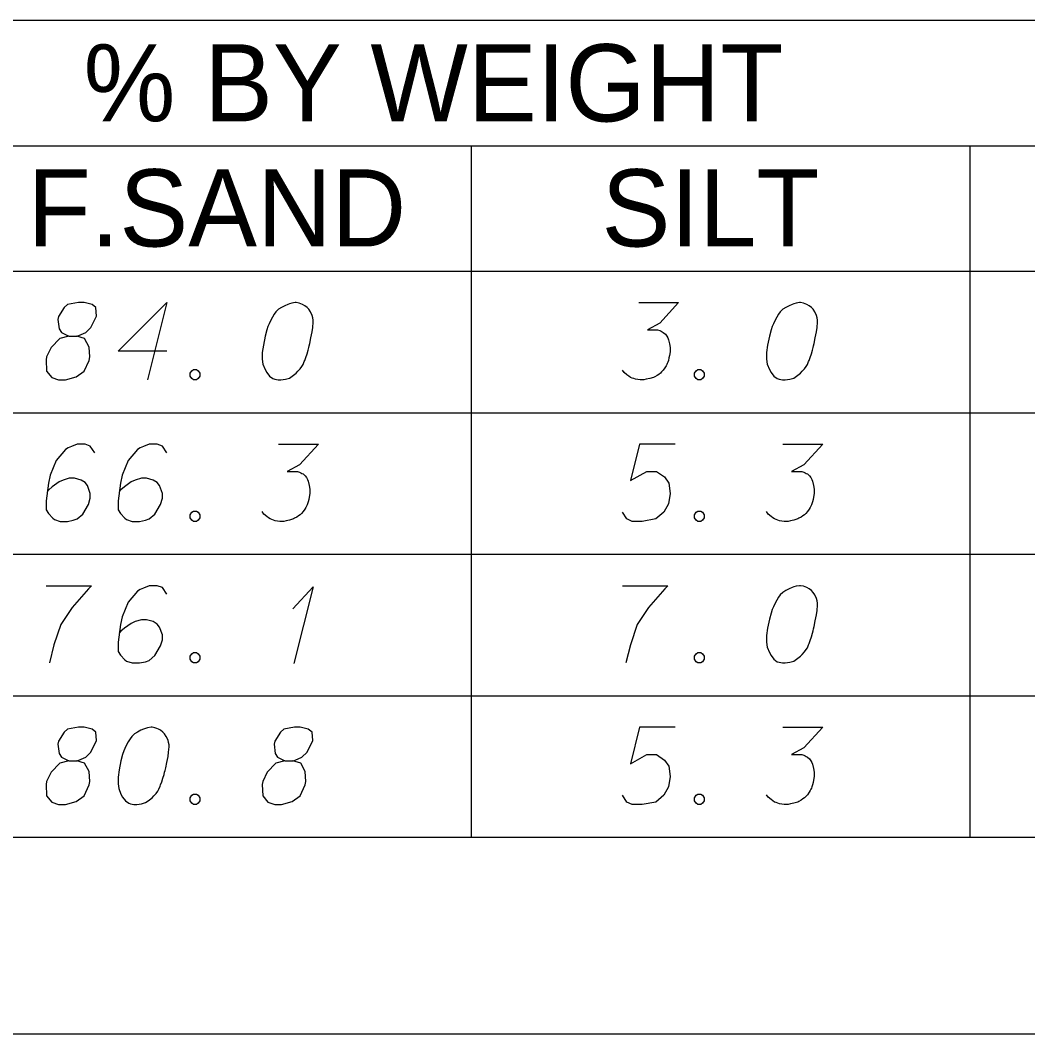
# Model space of a CAD drawing. Extents: x 2074207 to 2076812, y 516372 to 523312.
# Drawn here: x 2076560.1 to 2076622.7, y 516665.2 to 516728.2 of the extents above; entities that cross this region are included whole.
import ezdxf

# ---------------------------------------------------------------- set-up
doc = ezdxf.new("R2010")
doc.units = 0
for name, color, linetype in [('Prop DirtTable_ Soil Test Results - Outline (Major)', 7, 'Continuous'), ('Prop DirtTable_ Soil Test Results - Outline (Minor)', 7, 'Continuous'), ('Prop DirtTable_ Soil Test Results - Tx (Header - Small)', 7, 'Continuous'), ('Prop DirtTable_ Soil Test Results - Tx (Sample Data)', 7, 'Continuous')]:
    doc.layers.add(name, color=color, linetype=linetype)

msp = doc.modelspace()

# ---------------------------------------------------------------- linework, layer by layer
at = {"layer": 'Prop DirtTable_ Soil Test Results - Outline (Major)'}
for p, q in [((2076260.609, 516712.618), (2076811.903, 516712.618)), ((2076260.609, 516712.618), (2076811.903, 516712.618)), ((2076260.609, 516677.418), (2076811.903, 516677.418)), ((2076260.609, 516665.206), (2076811.903, 516665.206))]:
    msp.add_line(p, q, dxfattribs=at)
at = {"layer": 'Prop DirtTable_ Soil Test Results - Outline (Minor)'}
for p, q in [((2076260.609, 516728.218), (2076811.903, 516728.218)), ((2076526.074, 516720.418), (2076731.93, 516720.418)), ((2076588.114, 516720.418), (2076588.114, 516703.818)), ((2076619.134, 516703.818), (2076619.134, 516720.418)), ((2076260.609, 516703.818), (2076811.903, 516703.818)), ((2076260.609, 516703.818), (2076811.903, 516703.818)), ((2076588.114, 516703.818), (2076588.114, 516695.018)), ((2076619.134, 516695.018), (2076619.134, 516703.818)), ((2076260.609, 516695.018), (2076811.903, 516695.018)), ((2076260.609, 516695.018), (2076811.903, 516695.018)), ((2076588.114, 516695.018), (2076588.114, 516686.218)), ((2076619.134, 516686.218), (2076619.134, 516695.018)), ((2076260.609, 516686.218), (2076811.903, 516686.218)), ((2076260.609, 516686.218), (2076811.903, 516686.218)), ((2076588.114, 516686.218), (2076588.114, 516677.418)), ((2076619.134, 516677.418), (2076619.134, 516686.218)), ((2076260.609, 516677.418), (2076811.903, 516677.418))]:
    msp.add_line(p, q, dxfattribs=at)
at = {"layer": 'Prop DirtTable_ Soil Test Results - Tx (Sample Data)'}
for points in [[(2076563.087, 516708.583), (2076563.58, 516708.583), (2076563.722, 516708.621), (2076564.145, 516708.81), (2076564.462, 516709.112), (2076564.815, 516709.83), (2076564.78, 516710.359), (2076564.533, 516710.548), (2076564.039, 516710.662), (2076563.686, 516710.662), (2076563.016, 516710.548), (2076562.804, 516710.359), (2076562.452, 516709.792), (2076562.416, 516709.603), (2076562.487, 516709.036), (2076562.628, 516708.81), (2076563.087, 516708.583), (2076562.522, 516708.432), (2076561.993, 516707.865), (2076561.711, 516707.298), (2076561.676, 516707.109), (2076561.711, 516706.391), (2076562.028, 516706.013), (2076562.452, 516705.862), (2076562.875, 516705.862), (2076563.545, 516706.051), (2076564.039, 516706.391), (2076564.357, 516707.071), (2076564.392, 516707.298), (2076564.357, 516707.903), (2076564.074, 516708.432), (2076563.58, 516708.583)], [(2076569.189, 516707.638), (2076566.156, 516707.638), (2076569.189, 516710.662), (2076567.99, 516705.862)], [(2076577.232, 516710.662), (2076577.162, 516710.662), (2076576.95, 516710.624), (2076576.809, 516710.586), (2076576.703, 516710.548), (2076576.527, 516710.473), (2076576.315, 516710.359), (2076576.139, 516710.246), (2076575.962, 516710.095), (2076575.856, 516709.944), (2076575.751, 516709.755), (2076575.645, 516709.566), (2076575.539, 516709.339), (2076575.468, 516709.188), (2076575.398, 516708.961), (2076575.292, 516708.583), (2076575.186, 516708.016), (2076575.116, 516707.562), (2076575.116, 516707.147), (2076575.151, 516706.844), (2076575.292, 516706.504), (2076575.398, 516706.315), (2076575.574, 516706.088), (2076575.786, 516705.937), (2076575.892, 516705.899), (2076576.103, 516705.862), (2076576.28, 516705.862), (2076576.562, 516705.899), (2076576.809, 516705.975), (2076576.985, 516706.088), (2076577.232, 516706.277), (2076577.338, 516706.391), (2076577.479, 516706.542), (2076577.585, 516706.693), (2076577.655, 516706.807), (2076577.726, 516706.996), (2076577.761, 516707.071), (2076577.832, 516707.26), (2076577.902, 516707.487), (2076577.973, 516707.714), (2076578.008, 516707.865), (2076578.043, 516707.978), (2076578.079, 516708.129), (2076578.149, 516708.47), (2076578.185, 516708.659), (2076578.22, 516708.848), (2076578.255, 516709.112), (2076578.29, 516709.452), (2076578.29, 516709.566), (2076578.255, 516709.717), (2076578.22, 516709.868), (2076578.114, 516710.095), (2076578.008, 516710.246), (2076577.902, 516710.359), (2076577.761, 516710.473), (2076577.62, 516710.548), (2076577.514, 516710.586), (2076577.409, 516710.624), (2076577.232, 516710.662)], [(2076598.539, 516710.662), (2076601.008, 516710.662), (2076599.844, 516709.377), (2076599.068, 516708.961), (2076599.703, 516708.961), (2076599.844, 516708.923), (2076599.914, 516708.885), (2076599.985, 516708.848), (2076600.055, 516708.81), (2076600.197, 516708.696), (2076600.267, 516708.583), (2076600.338, 516708.47), (2076600.373, 516708.356), (2076600.443, 516708.092), (2076600.479, 516707.865), (2076600.479, 516707.751), (2076600.479, 516707.6), (2076600.443, 516707.373), (2076600.408, 516707.222), (2076600.373, 516707.071), (2076600.338, 516706.958), (2076600.302, 516706.882), (2076600.267, 516706.807), (2076600.232, 516706.731), (2076600.161, 516706.618), (2076600.055, 516706.466), (2076599.95, 516706.353), (2076599.879, 516706.277), (2076599.773, 516706.202), (2076599.667, 516706.126), (2076599.526, 516706.051), (2076599.456, 516706.013), (2076599.209, 516705.937), (2076598.997, 516705.899), (2076598.856, 516705.862), (2076598.609, 516705.862), (2076598.327, 516705.899), (2076598.221, 516705.937), (2076598.115, 516705.975), (2076598.009, 516706.013), (2076597.904, 516706.088), (2076597.798, 516706.164), (2076597.621, 516706.315), (2076597.516, 516706.466)], [(2076608.592, 516710.662), (2076608.522, 516710.662), (2076608.31, 516710.624), (2076608.169, 516710.586), (2076608.063, 516710.548), (2076607.887, 516710.473), (2076607.675, 516710.359), (2076607.499, 516710.246), (2076607.322, 516710.095), (2076607.216, 516709.944), (2076607.111, 516709.755), (2076607.005, 516709.566), (2076606.899, 516709.339), (2076606.828, 516709.188), (2076606.758, 516708.961), (2076606.652, 516708.583), (2076606.546, 516708.016), (2076606.476, 516707.562), (2076606.476, 516707.147), (2076606.511, 516706.844), (2076606.652, 516706.504), (2076606.758, 516706.315), (2076606.934, 516706.088), (2076607.146, 516705.937), (2076607.252, 516705.899), (2076607.463, 516705.862), (2076607.64, 516705.862), (2076607.922, 516705.899), (2076608.169, 516705.975), (2076608.345, 516706.088), (2076608.592, 516706.277), (2076608.698, 516706.391), (2076608.839, 516706.542), (2076608.945, 516706.693), (2076609.015, 516706.807), (2076609.086, 516706.996), (2076609.121, 516707.071), (2076609.192, 516707.26), (2076609.262, 516707.487), (2076609.333, 516707.714), (2076609.368, 516707.865), (2076609.403, 516707.978), (2076609.439, 516708.129), (2076609.509, 516708.47), (2076609.545, 516708.659), (2076609.58, 516708.848), (2076609.615, 516709.112), (2076609.65, 516709.452), (2076609.65, 516709.566), (2076609.615, 516709.717), (2076609.58, 516709.868), (2076609.474, 516710.095), (2076609.368, 516710.246), (2076609.262, 516710.359), (2076609.121, 516710.473), (2076608.98, 516710.548), (2076608.874, 516710.586), (2076608.769, 516710.624), (2076608.592, 516710.662)], [(2076570.847, 516706.504), (2076571.024, 516706.504), (2076571.129, 516706.429), (2076571.235, 516706.277), (2076571.235, 516706.088), (2076571.129, 516705.937), (2076571.024, 516705.862), (2076570.847, 516705.862), (2076570.741, 516705.937), (2076570.636, 516706.088), (2076570.636, 516706.277), (2076570.741, 516706.429), (2076570.847, 516706.504)], [(2076602.207, 516706.504), (2076602.384, 516706.504), (2076602.489, 516706.429), (2076602.595, 516706.277), (2076602.595, 516706.088), (2076602.489, 516705.937), (2076602.384, 516705.862), (2076602.207, 516705.862), (2076602.101, 516705.937), (2076601.996, 516706.088), (2076601.996, 516706.277), (2076602.101, 516706.429), (2076602.207, 516706.504)], [(2076564.709, 516701.333), (2076564.427, 516701.748), (2076564.11, 516701.862), (2076563.616, 516701.862), (2076563.263, 516701.711), (2076563.051, 516701.635), (2076562.875, 516701.522), (2076562.311, 516700.841), (2076561.923, 516699.934), (2076561.817, 516699.443), (2076561.676, 516698.347), (2076561.676, 516697.78), (2076561.817, 516697.553), (2076562.099, 516697.251), (2076562.205, 516697.175), (2076562.558, 516697.062), (2076563.016, 516697.062), (2076563.369, 516697.137), (2076563.616, 516697.213), (2076563.969, 516697.515), (2076564.321, 516698.12), (2076564.427, 516698.498), (2076564.427, 516698.8), (2076564.251, 516699.292), (2076564.11, 516699.481), (2076563.863, 516699.632), (2076563.439, 516699.745), (2076563.122, 516699.745), (2076562.734, 516699.632), (2076562.487, 516699.518), (2076562.064, 516699.216), (2076561.852, 516699.027), (2076561.746, 516698.914)], [(2076569.189, 516701.333), (2076568.907, 516701.748), (2076568.59, 516701.862), (2076568.096, 516701.862), (2076567.743, 516701.711), (2076567.531, 516701.635), (2076567.355, 516701.522), (2076566.791, 516700.841), (2076566.403, 516699.934), (2076566.297, 516699.443), (2076566.156, 516698.347), (2076566.156, 516697.78), (2076566.297, 516697.553), (2076566.579, 516697.251), (2076566.685, 516697.175), (2076567.038, 516697.062), (2076567.496, 516697.062), (2076567.849, 516697.137), (2076568.096, 516697.213), (2076568.449, 516697.515), (2076568.801, 516698.12), (2076568.907, 516698.498), (2076568.907, 516698.8), (2076568.731, 516699.292), (2076568.59, 516699.481), (2076568.343, 516699.632), (2076567.919, 516699.745), (2076567.602, 516699.745), (2076567.214, 516699.632), (2076566.967, 516699.518), (2076566.544, 516699.216), (2076566.332, 516699.027), (2076566.226, 516698.914)], [(2076576.139, 516701.862), (2076578.608, 516701.862), (2076577.444, 516700.577), (2076576.668, 516700.161), (2076577.303, 516700.161), (2076577.444, 516700.123), (2076577.514, 516700.085), (2076577.585, 516700.048), (2076577.655, 516700.01), (2076577.797, 516699.896), (2076577.867, 516699.783), (2076577.938, 516699.67), (2076577.973, 516699.556), (2076578.043, 516699.292), (2076578.079, 516699.065), (2076578.079, 516698.951), (2076578.079, 516698.8), (2076578.043, 516698.573), (2076578.008, 516698.422), (2076577.973, 516698.271), (2076577.938, 516698.158), (2076577.902, 516698.082), (2076577.867, 516698.007), (2076577.832, 516697.931), (2076577.761, 516697.818), (2076577.655, 516697.666), (2076577.55, 516697.553), (2076577.479, 516697.477), (2076577.373, 516697.402), (2076577.267, 516697.326), (2076577.126, 516697.251), (2076577.056, 516697.213), (2076576.809, 516697.137), (2076576.597, 516697.099), (2076576.456, 516697.062), (2076576.209, 516697.062), (2076575.927, 516697.099), (2076575.821, 516697.137), (2076575.715, 516697.175), (2076575.609, 516697.213), (2076575.504, 516697.288), (2076575.398, 516697.364), (2076575.221, 516697.515), (2076575.116, 516697.666)], [(2076600.796, 516701.862), (2076598.574, 516701.862), (2076598.009, 516699.594), (2076599.032, 516700.161), (2076599.632, 516700.161), (2076600.126, 516699.821), (2076600.408, 516699.443), (2076600.479, 516698.8), (2076600.373, 516698.158), (2076600.091, 516697.629), (2076599.597, 516697.213), (2076598.75, 516697.062), (2076598.115, 516697.062), (2076597.798, 516697.213), (2076597.516, 516697.629)], [(2076607.499, 516701.862), (2076609.968, 516701.862), (2076608.804, 516700.577), (2076608.028, 516700.161), (2076608.663, 516700.161), (2076608.804, 516700.123), (2076608.874, 516700.085), (2076608.945, 516700.048), (2076609.015, 516700.01), (2076609.157, 516699.896), (2076609.227, 516699.783), (2076609.298, 516699.67), (2076609.333, 516699.556), (2076609.403, 516699.292), (2076609.439, 516699.065), (2076609.439, 516698.951), (2076609.439, 516698.8), (2076609.403, 516698.573), (2076609.368, 516698.422), (2076609.333, 516698.271), (2076609.298, 516698.158), (2076609.262, 516698.082), (2076609.227, 516698.007), (2076609.192, 516697.931), (2076609.121, 516697.818), (2076609.015, 516697.666), (2076608.91, 516697.553), (2076608.839, 516697.477), (2076608.733, 516697.402), (2076608.627, 516697.326), (2076608.486, 516697.251), (2076608.416, 516697.213), (2076608.169, 516697.137), (2076607.957, 516697.099), (2076607.816, 516697.062), (2076607.569, 516697.062), (2076607.287, 516697.099), (2076607.181, 516697.137), (2076607.075, 516697.175), (2076606.969, 516697.213), (2076606.864, 516697.288), (2076606.758, 516697.364), (2076606.581, 516697.515), (2076606.476, 516697.666)], [(2076570.847, 516697.704), (2076571.024, 516697.704), (2076571.129, 516697.629), (2076571.235, 516697.477), (2076571.235, 516697.288), (2076571.129, 516697.137), (2076571.024, 516697.062), (2076570.847, 516697.062), (2076570.741, 516697.137), (2076570.636, 516697.288), (2076570.636, 516697.477), (2076570.741, 516697.629), (2076570.847, 516697.704)], [(2076602.207, 516697.704), (2076602.384, 516697.704), (2076602.489, 516697.629), (2076602.595, 516697.477), (2076602.595, 516697.288), (2076602.489, 516697.137), (2076602.384, 516697.062), (2076602.207, 516697.062), (2076602.101, 516697.137), (2076601.996, 516697.288), (2076601.996, 516697.477), (2076602.101, 516697.629), (2076602.207, 516697.704)], [(2076561.676, 516693.062), (2076564.498, 516693.062), (2076564.321, 516692.873), (2076563.298, 516691.701), (2076562.593, 516690.643), (2076562.169, 516689.396), (2076561.887, 516688.262)], [(2076569.189, 516692.533), (2076568.907, 516692.948), (2076568.59, 516693.062), (2076568.096, 516693.062), (2076567.743, 516692.911), (2076567.531, 516692.835), (2076567.355, 516692.722), (2076566.791, 516692.041), (2076566.403, 516691.134), (2076566.297, 516690.643), (2076566.156, 516689.547), (2076566.156, 516688.98), (2076566.297, 516688.753), (2076566.579, 516688.451), (2076566.685, 516688.375), (2076567.038, 516688.262), (2076567.496, 516688.262), (2076567.849, 516688.337), (2076568.096, 516688.413), (2076568.449, 516688.715), (2076568.801, 516689.32), (2076568.907, 516689.698), (2076568.907, 516690), (2076568.731, 516690.492), (2076568.59, 516690.681), (2076568.343, 516690.832), (2076567.919, 516690.945), (2076567.602, 516690.945), (2076567.214, 516690.832), (2076566.967, 516690.718), (2076566.544, 516690.416), (2076566.332, 516690.227), (2076566.226, 516690.114)], [(2076577.02, 516691.625), (2076578.29, 516692.986), (2076577.091, 516688.224)], [(2076597.516, 516693.062), (2076600.338, 516693.062), (2076600.161, 516692.873), (2076599.138, 516691.701), (2076598.433, 516690.643), (2076598.009, 516689.396), (2076597.727, 516688.262)], [(2076608.592, 516693.062), (2076608.522, 516693.062), (2076608.31, 516693.024), (2076608.169, 516692.986), (2076608.063, 516692.948), (2076607.887, 516692.873), (2076607.675, 516692.759), (2076607.499, 516692.646), (2076607.322, 516692.495), (2076607.216, 516692.344), (2076607.111, 516692.155), (2076607.005, 516691.966), (2076606.899, 516691.739), (2076606.828, 516691.588), (2076606.758, 516691.361), (2076606.652, 516690.983), (2076606.546, 516690.416), (2076606.476, 516689.962), (2076606.476, 516689.547), (2076606.511, 516689.244), (2076606.652, 516688.904), (2076606.758, 516688.715), (2076606.934, 516688.488), (2076607.146, 516688.337), (2076607.252, 516688.299), (2076607.463, 516688.262), (2076607.64, 516688.262), (2076607.922, 516688.299), (2076608.169, 516688.375), (2076608.345, 516688.488), (2076608.592, 516688.677), (2076608.698, 516688.791), (2076608.839, 516688.942), (2076608.945, 516689.093), (2076609.015, 516689.207), (2076609.086, 516689.396), (2076609.121, 516689.471), (2076609.192, 516689.66), (2076609.262, 516689.887), (2076609.333, 516690.114), (2076609.368, 516690.265), (2076609.403, 516690.378), (2076609.439, 516690.529), (2076609.509, 516690.87), (2076609.545, 516691.059), (2076609.58, 516691.248), (2076609.615, 516691.512), (2076609.65, 516691.852), (2076609.65, 516691.966), (2076609.615, 516692.117), (2076609.58, 516692.268), (2076609.474, 516692.495), (2076609.368, 516692.646), (2076609.262, 516692.759), (2076609.121, 516692.873), (2076608.98, 516692.948), (2076608.874, 516692.986), (2076608.769, 516693.024), (2076608.592, 516693.062)], [(2076570.847, 516688.904), (2076571.024, 516688.904), (2076571.129, 516688.829), (2076571.235, 516688.677), (2076571.235, 516688.488), (2076571.129, 516688.337), (2076571.024, 516688.262), (2076570.847, 516688.262), (2076570.741, 516688.337), (2076570.636, 516688.488), (2076570.636, 516688.677), (2076570.741, 516688.829), (2076570.847, 516688.904)], [(2076602.207, 516688.904), (2076602.384, 516688.904), (2076602.489, 516688.829), (2076602.595, 516688.677), (2076602.595, 516688.488), (2076602.489, 516688.337), (2076602.384, 516688.262), (2076602.207, 516688.262), (2076602.101, 516688.337), (2076601.996, 516688.488), (2076601.996, 516688.677), (2076602.101, 516688.829), (2076602.207, 516688.904)], [(2076563.087, 516682.183), (2076563.58, 516682.183), (2076563.722, 516682.221), (2076564.145, 516682.41), (2076564.462, 516682.712), (2076564.815, 516683.43), (2076564.78, 516683.959), (2076564.533, 516684.148), (2076564.039, 516684.262), (2076563.686, 516684.262), (2076563.016, 516684.148), (2076562.804, 516683.959), (2076562.452, 516683.392), (2076562.416, 516683.203), (2076562.487, 516682.636), (2076562.628, 516682.41), (2076563.087, 516682.183), (2076562.522, 516682.032), (2076561.993, 516681.465), (2076561.711, 516680.898), (2076561.676, 516680.709), (2076561.711, 516679.991), (2076562.028, 516679.613), (2076562.452, 516679.462), (2076562.875, 516679.462), (2076563.545, 516679.651), (2076564.039, 516679.991), (2076564.357, 516680.671), (2076564.392, 516680.898), (2076564.357, 516681.503), (2076564.074, 516682.032), (2076563.58, 516682.183)], [(2076568.272, 516684.262), (2076568.202, 516684.262), (2076567.99, 516684.224), (2076567.849, 516684.186), (2076567.743, 516684.148), (2076567.567, 516684.073), (2076567.355, 516683.959), (2076567.179, 516683.846), (2076567.002, 516683.695), (2076566.896, 516683.544), (2076566.791, 516683.355), (2076566.685, 516683.166), (2076566.579, 516682.939), (2076566.508, 516682.788), (2076566.438, 516682.561), (2076566.332, 516682.183), (2076566.226, 516681.616), (2076566.156, 516681.162), (2076566.156, 516680.747), (2076566.191, 516680.444), (2076566.332, 516680.104), (2076566.438, 516679.915), (2076566.614, 516679.688), (2076566.826, 516679.537), (2076566.932, 516679.499), (2076567.143, 516679.462), (2076567.32, 516679.462), (2076567.602, 516679.499), (2076567.849, 516679.575), (2076568.025, 516679.688), (2076568.272, 516679.877), (2076568.378, 516679.991), (2076568.519, 516680.142), (2076568.625, 516680.293), (2076568.695, 516680.407), (2076568.766, 516680.596), (2076568.801, 516680.671), (2076568.872, 516680.86), (2076568.942, 516681.087), (2076569.013, 516681.314), (2076569.048, 516681.465), (2076569.083, 516681.578), (2076569.119, 516681.729), (2076569.189, 516682.07), (2076569.225, 516682.259), (2076569.26, 516682.448), (2076569.295, 516682.712), (2076569.33, 516683.052), (2076569.33, 516683.166), (2076569.295, 516683.317), (2076569.26, 516683.468), (2076569.154, 516683.695), (2076569.048, 516683.846), (2076568.942, 516683.959), (2076568.801, 516684.073), (2076568.66, 516684.148), (2076568.554, 516684.186), (2076568.449, 516684.224), (2076568.272, 516684.262)], [(2076576.527, 516682.183), (2076577.02, 516682.183), (2076577.162, 516682.221), (2076577.585, 516682.41), (2076577.902, 516682.712), (2076578.255, 516683.43), (2076578.22, 516683.959), (2076577.973, 516684.148), (2076577.479, 516684.262), (2076577.126, 516684.262), (2076576.456, 516684.148), (2076576.244, 516683.959), (2076575.892, 516683.392), (2076575.856, 516683.203), (2076575.927, 516682.636), (2076576.068, 516682.41), (2076576.527, 516682.183), (2076575.962, 516682.032), (2076575.433, 516681.465), (2076575.151, 516680.898), (2076575.116, 516680.709), (2076575.151, 516679.991), (2076575.468, 516679.613), (2076575.892, 516679.462), (2076576.315, 516679.462), (2076576.985, 516679.651), (2076577.479, 516679.991), (2076577.797, 516680.671), (2076577.832, 516680.898), (2076577.797, 516681.503), (2076577.514, 516682.032), (2076577.02, 516682.183)], [(2076600.796, 516684.262), (2076598.574, 516684.262), (2076598.009, 516681.994), (2076599.032, 516682.561), (2076599.632, 516682.561), (2076600.126, 516682.221), (2076600.408, 516681.843), (2076600.479, 516681.2), (2076600.373, 516680.558), (2076600.091, 516680.029), (2076599.597, 516679.613), (2076598.75, 516679.462), (2076598.115, 516679.462), (2076597.798, 516679.613), (2076597.516, 516680.029)], [(2076607.499, 516684.262), (2076609.968, 516684.262), (2076608.804, 516682.977), (2076608.028, 516682.561), (2076608.663, 516682.561), (2076608.804, 516682.523), (2076608.874, 516682.485), (2076608.945, 516682.448), (2076609.015, 516682.41), (2076609.157, 516682.296), (2076609.227, 516682.183), (2076609.298, 516682.07), (2076609.333, 516681.956), (2076609.403, 516681.692), (2076609.439, 516681.465), (2076609.439, 516681.351), (2076609.439, 516681.2), (2076609.403, 516680.973), (2076609.368, 516680.822), (2076609.333, 516680.671), (2076609.298, 516680.558), (2076609.262, 516680.482), (2076609.227, 516680.407), (2076609.192, 516680.331), (2076609.121, 516680.218), (2076609.015, 516680.066), (2076608.91, 516679.953), (2076608.839, 516679.877), (2076608.733, 516679.802), (2076608.627, 516679.726), (2076608.486, 516679.651), (2076608.416, 516679.613), (2076608.169, 516679.537), (2076607.957, 516679.499), (2076607.816, 516679.462), (2076607.569, 516679.462), (2076607.287, 516679.499), (2076607.181, 516679.537), (2076607.075, 516679.575), (2076606.969, 516679.613), (2076606.864, 516679.688), (2076606.758, 516679.764), (2076606.581, 516679.915), (2076606.476, 516680.066)], [(2076570.847, 516680.104), (2076571.024, 516680.104), (2076571.129, 516680.029), (2076571.235, 516679.877), (2076571.235, 516679.688), (2076571.129, 516679.537), (2076571.024, 516679.462), (2076570.847, 516679.462), (2076570.741, 516679.537), (2076570.636, 516679.688), (2076570.636, 516679.877), (2076570.741, 516680.029), (2076570.847, 516680.104)], [(2076602.207, 516680.104), (2076602.384, 516680.104), (2076602.489, 516680.029), (2076602.595, 516679.877), (2076602.595, 516679.688), (2076602.489, 516679.537), (2076602.384, 516679.462), (2076602.207, 516679.462), (2076602.101, 516679.537), (2076601.996, 516679.688), (2076601.996, 516679.877), (2076602.101, 516680.029), (2076602.207, 516680.104)]]:
    msp.add_lwpolyline(points, dxfattribs=at)

# ---------------------------------------------------------------- texts
at = {"layer": 'Prop DirtTable_ Soil Test Results - Tx (Header - Small)'}
for s, height, p in [('% BY WEIGHT', 4.79998, (2076564.009, 516721.928)), ('F.SAND', 4.8, (2076560.529, 516714.153)), ('SILT', 4.8, (2076596.215, 516714.153))]:
    msp.add_text(s, height=height, dxfattribs=at).set_placement(p)

doc.saveas('drawing.dxf')
